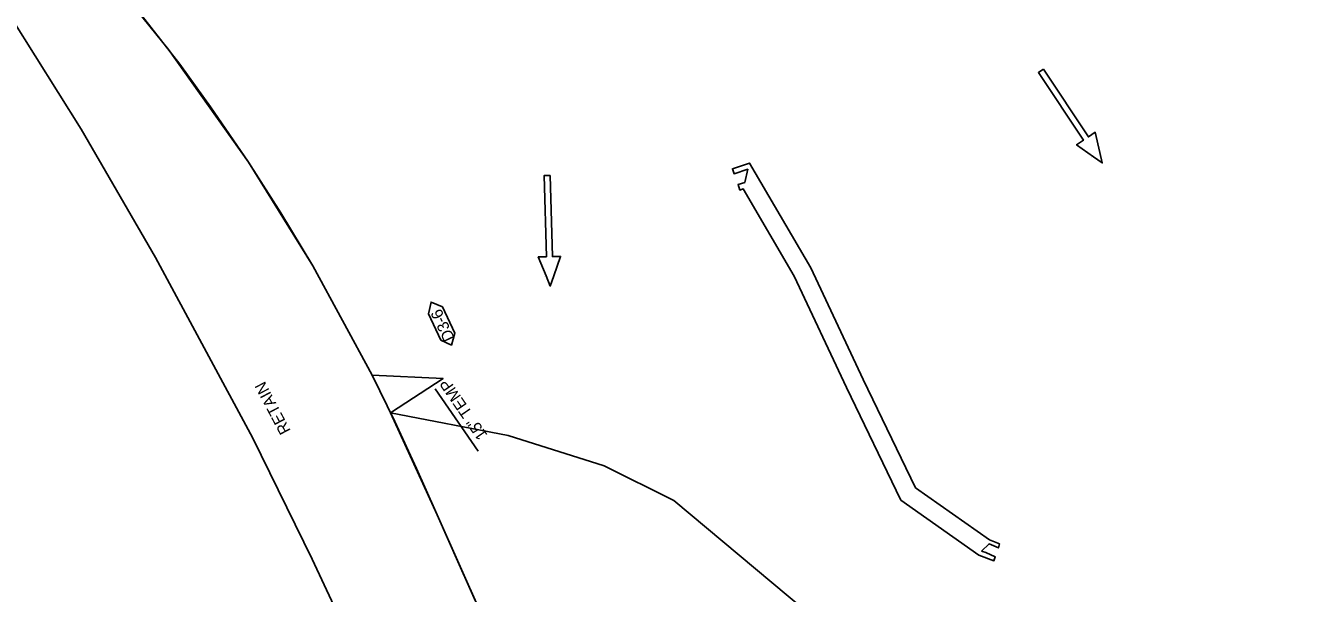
# Model space of a CAD drawing. Extents: x 465700 to 483515, y 488970 to 507540.
# Drawn here: x 477587 to 478138, y 499494 to 499740 of the extents above; entities that cross this region are included whole.
import ezdxf

# ---------------------------------------------------------------- set-up
doc = ezdxf.new("R2010")
doc.units = 0
for name, color, linetype in [('Default', 7, 'Continuous'), ('Exist Plan Preparation Drainage Flow Arrows', 7, 'Continuous'), ('Exist Plan Preparation Watershed Blue', 7, 'Continuous'), ('Prop Drainage Structure Box Number Symbol CELL', 7, 'Continuous'), ('Prop Drainage Structure Pipe Collar Label', 7, 'Continuous'), ('Prop Drainage Structure Pipe Side Drain 15in', 7, 'Continuous'), ('Prop Drainage Structure Pipe Side Drain 15in Label', 7, 'Continuous'), ('Scratch_Level_4', 7, 'Continuous')]:
    doc.layers.add(name, color=color, linetype=linetype)

# ---------------------------------------------------------------- blocks, each defined once
blk = doc.blocks.new('Existing ground flow arrow')
at = {"layer": 'Default'}
blk.add_line((2.5, -4.33), (2.5, -4.33), dxfattribs=at)
blk.add_lwpolyline([(-1.29, -47.2), (-1.28, -12.53), (-4.77, -12.53), (-1.65, -4.33), (0, 0), (1.65, -4.33), (4.78, -12.53), (1.28, -12.52), (1.29, -47.19), (0, -47.2)], close=True, dxfattribs=at)

msp = doc.modelspace()

# ---------------------------------------------------------------- linework, layer by layer
at = {"layer": 'Exist Plan Preparation Watershed Blue'}
for points in [[(477618.98, 499766.16), (477648.78, 499729.18), (477683.33, 499680.45), (477711.15, 499635.72), (477736.76, 499588.43), (477746.56, 499568.42), (477759.49, 499540.06), (477764.82, 499528.09), (477773.77, 499507.99), (477803.41, 499441.41), (477841.35, 499356.21), (477862.6, 499308.49), (477888.75, 499247.35), (477905.42, 499201.8), (477913.55, 499176.64), (477929.73, 499118.92)], [(478176.46, 499333.67), (478105.39, 499349.47), (478080.37, 499359.96), (478035.25, 499385.83), (477983.32, 499428.7), (477944.68, 499469.38), (477867.06, 499534.37), (477836.92, 499549.34), (477795.57, 499562.48), (477744.68, 499572.28), (477767.35, 499587.11), (477736.76, 499588.43), (477711.15, 499635.72), (477697.3, 499658.65), (477683.33, 499680.45), (477666.94, 499704.35), (477653.6, 499722.79), (477636.96, 499744.16)], [(477858.24, 499093.41), (477832.51, 499190.03), (477802.27, 499285.34), (477767.58, 499379.12), (477747.49, 499427.65), (477728.52, 499471.17), (477710.77, 499509.04), (477685.16, 499561.27), (477643.08, 499639.33), (477611.01, 499694.79), (477581.24, 499742.27)], [(477944.68, 499469.38), (477867.06, 499534.37), (477836.92, 499549.34), (477795.57, 499562.48), (477744.68, 499572.28), (477746.56, 499568.42), (477755.87, 499548.18), (477764.82, 499528.09), (477773.77, 499507.99), (477803.41, 499441.41)]]:
    msp.add_lwpolyline(points, dxfattribs=at)
at = {"layer": 'Prop Drainage Structure Box Number Symbol CELL'}
msp.add_lwpolyline([(477766.41, 499603.6), (477761.02, 499615), (477762.19, 499620.09), (477767.11, 499618.05), (477772.5, 499606.66), (477770.97, 499601.51), (477766.41, 499603.6)], dxfattribs=at)
at = {"layer": 'Prop Drainage Structure Pipe Side Drain 15in'}
msp.add_line((477763.96, 499582.59), (477782.48, 499555.62), dxfattribs=at)
at = {"layer": 'Scratch_Level_4'}
for points in [[(478000, 499512.39), (478001.94, 499511.91), (478005.97, 499509.99), (478005.4, 499508.33), (477998.85, 499510.76), (477965.23, 499534.49), (477941.64, 499583.12), (477919.07, 499631.26), (477897.07, 499668.94), (477895.66, 499668.46), (477894.86, 499670.79), (477897.74, 499671.76), (477899.04, 499677.46), (477893.15, 499675.52), (477892.43, 499677.67), (477899.83, 499680.09), (477926.23, 499634.81), (477948.86, 499586.56), (477971.53, 499539.83), (478003.46, 499517.3), (478007.77, 499515.62), (478007.33, 499513.88), (478003.31, 499515.65)], [(477846, 499344.45), (477895.99, 499359.48), (478035.25, 499385.83), (477983.32, 499428.7), (477944.68, 499469.38), (477867.06, 499534.37), (477836.92, 499549.34), (477795.57, 499562.48), (477744.68, 499572.28), (477764.82, 499528.09), (477803.41, 499441.41), (477841.35, 499356.21)], [(477846, 499344.45), (477862.6, 499308.49), (477871.55, 499288.39), (477929.76, 499306.12), (478105.39, 499349.47), (478080.37, 499359.96), (478035.25, 499385.83), (477983.32, 499428.7), (477944.68, 499469.38), (477867.06, 499534.37), (477836.92, 499549.34), (477795.57, 499562.48), (477744.68, 499572.28), (477764.82, 499528.09), (477803.41, 499441.41), (477841.35, 499356.21)]]:
    msp.add_lwpolyline(points, close=True, dxfattribs=at)

# ---------------------------------------------------------------- block references
at = {"layer": 'Exist Plan Preparation Drainage Flow Arrows', "yscale": 1.0124070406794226}
for p, xscale, rotation in [((478052.2, 499680.15), 1.0124070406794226, -146.3224176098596), ((477813.7, 499627), 1.0124070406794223, -178.37589998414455)]:
    msp.add_blockref('Existing ground flow arrow', p, dxfattribs=dict(at, xscale=xscale, rotation=rotation))

# ---------------------------------------------------------------- texts
at = {"layer": 'Prop Drainage Structure Box Number Symbol CELL'}
msp.add_text('D3-6', height=5, rotation=115.2909, dxfattribs=at).set_placement((477772.52, 499604.45))
at = {"layer": 'Prop Drainage Structure Pipe Collar Label'}
msp.add_text('RETAIN', height=5, rotation=117.8251, dxfattribs=at).set_placement((477701.65, 499564.51))
at = {"layer": 'Prop Drainage Structure Pipe Side Drain 15in Label'}
msp.add_text('15" TEMP', height=5, rotation=124.4853, dxfattribs=at).set_placement((477786.79, 499562.59))

doc.saveas('drawing.dxf')
